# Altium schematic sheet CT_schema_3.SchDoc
size 206 x 169 mm
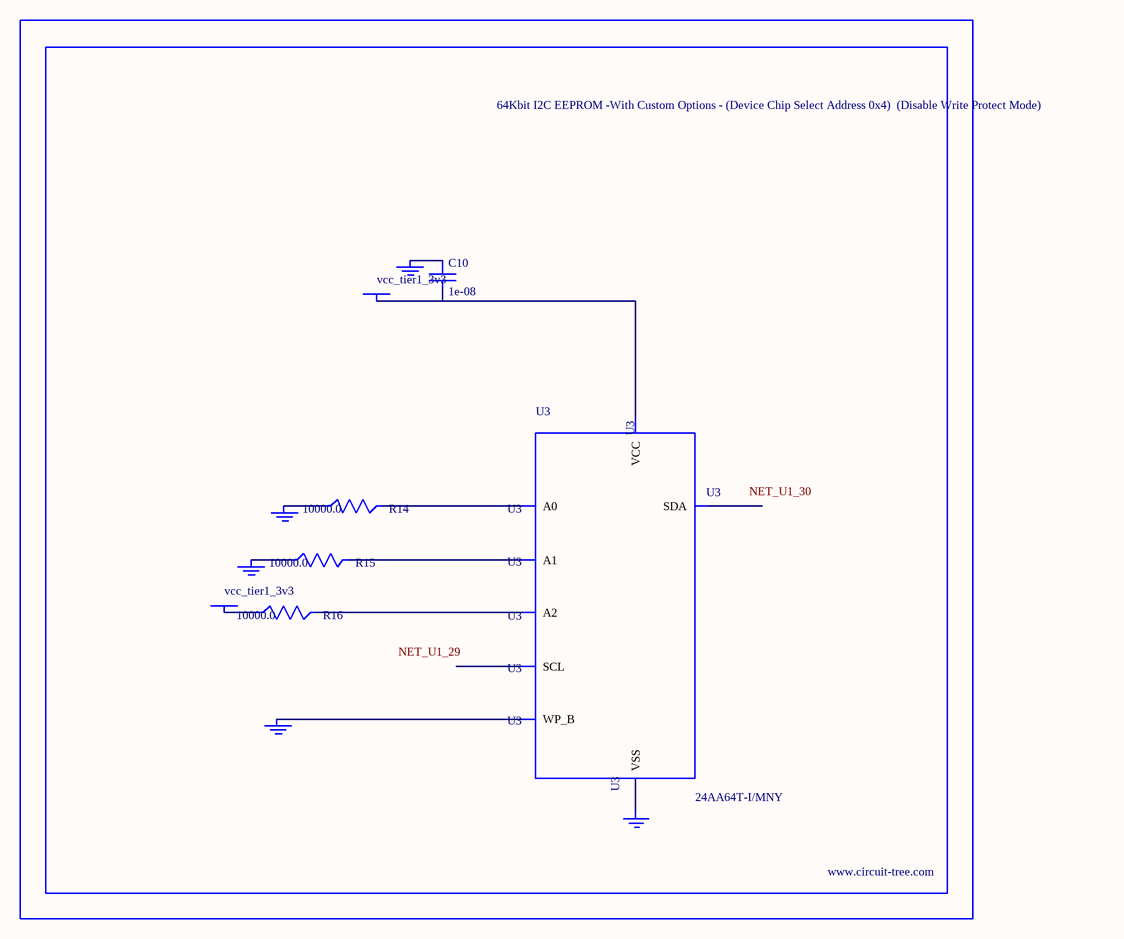
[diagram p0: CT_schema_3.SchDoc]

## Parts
BORDER2  (no value)
C10  1e-08  [C0402]
GND_INSTANCE_2_0  (no value)
GND_INSTANCE_2_1  (no value)
GND_INSTANCE_2_2  (no value)
GND_INSTANCE_2_3  (no value)
GND_INSTANCE_2_4  (no value)
POWER_INSTANCE_2_0  vcc_tier1_3v3
POWER_INSTANCE_2_1  vcc_tier1_3v3
R14  10000.0  [R0603]
R15  10000.0  [R0603]
R16  10000.0  [R0603]
U3  24AA64T-I/MNY  [TDFN-8/6MM]

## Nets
NetC10_1: C10.1 GND_INSTANCE_2_3.0(GND)
NetC10_2: C10.2 POWER_INSTANCE_2_1.0(PWR) U3.8(VCC)
NetGND_INSTANCE_2_0_0: GND_INSTANCE_2_0.0(GND) R14.1
NetGND_INSTANCE_2_1_0: GND_INSTANCE_2_1.0(GND) R15.1
NetGND_INSTANCE_2_2_0: GND_INSTANCE_2_2.0(GND) U3.7(WP_B)
NetGND_INSTANCE_2_4_0: GND_INSTANCE_2_4.0(GND) U3.4(VSS)
NetPOWER_INSTANCE_2_0_0: POWER_INSTANCE_2_0.0(PWR) R16.1
NetR14_2: R14.2 U3.1(A0)
NetR15_2: R15.2 U3.2(A1)
NetR16_2: R16.2 U3.3(A2)

Not connected (* = marked no-connect by the designer): U3 5(SDA) 6(SCL)

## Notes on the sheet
- Labels drawn without touching a wire or pin: NET_U1_29, NET_U1_30

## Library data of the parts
BORDER2 = BORDER_PAGE2
C10 = C0402C103K3RAC
GND_INSTANCE_2_0-GND_INSTANCE_2_4 = GND
POWER_INSTANCE_2_0 POWER_INSTANCE_2_1 = PWR
R14-R16 = RC0603JR-0710KL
